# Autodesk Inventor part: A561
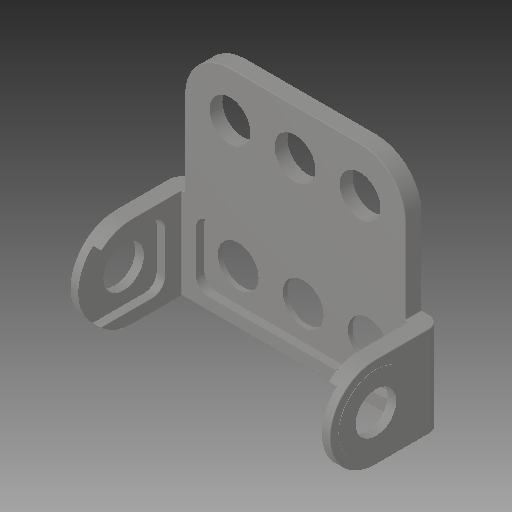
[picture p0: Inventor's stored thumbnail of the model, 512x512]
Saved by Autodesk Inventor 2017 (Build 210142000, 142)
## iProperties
Part Number: A561
Material: Générique
Document SubType Name: Modeling
Designer: ficho
Density: 1 g/cm^3
Appearance: Par défaut
Author: ficho
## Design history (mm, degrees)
feature "Solid1"
node "Solide1"
